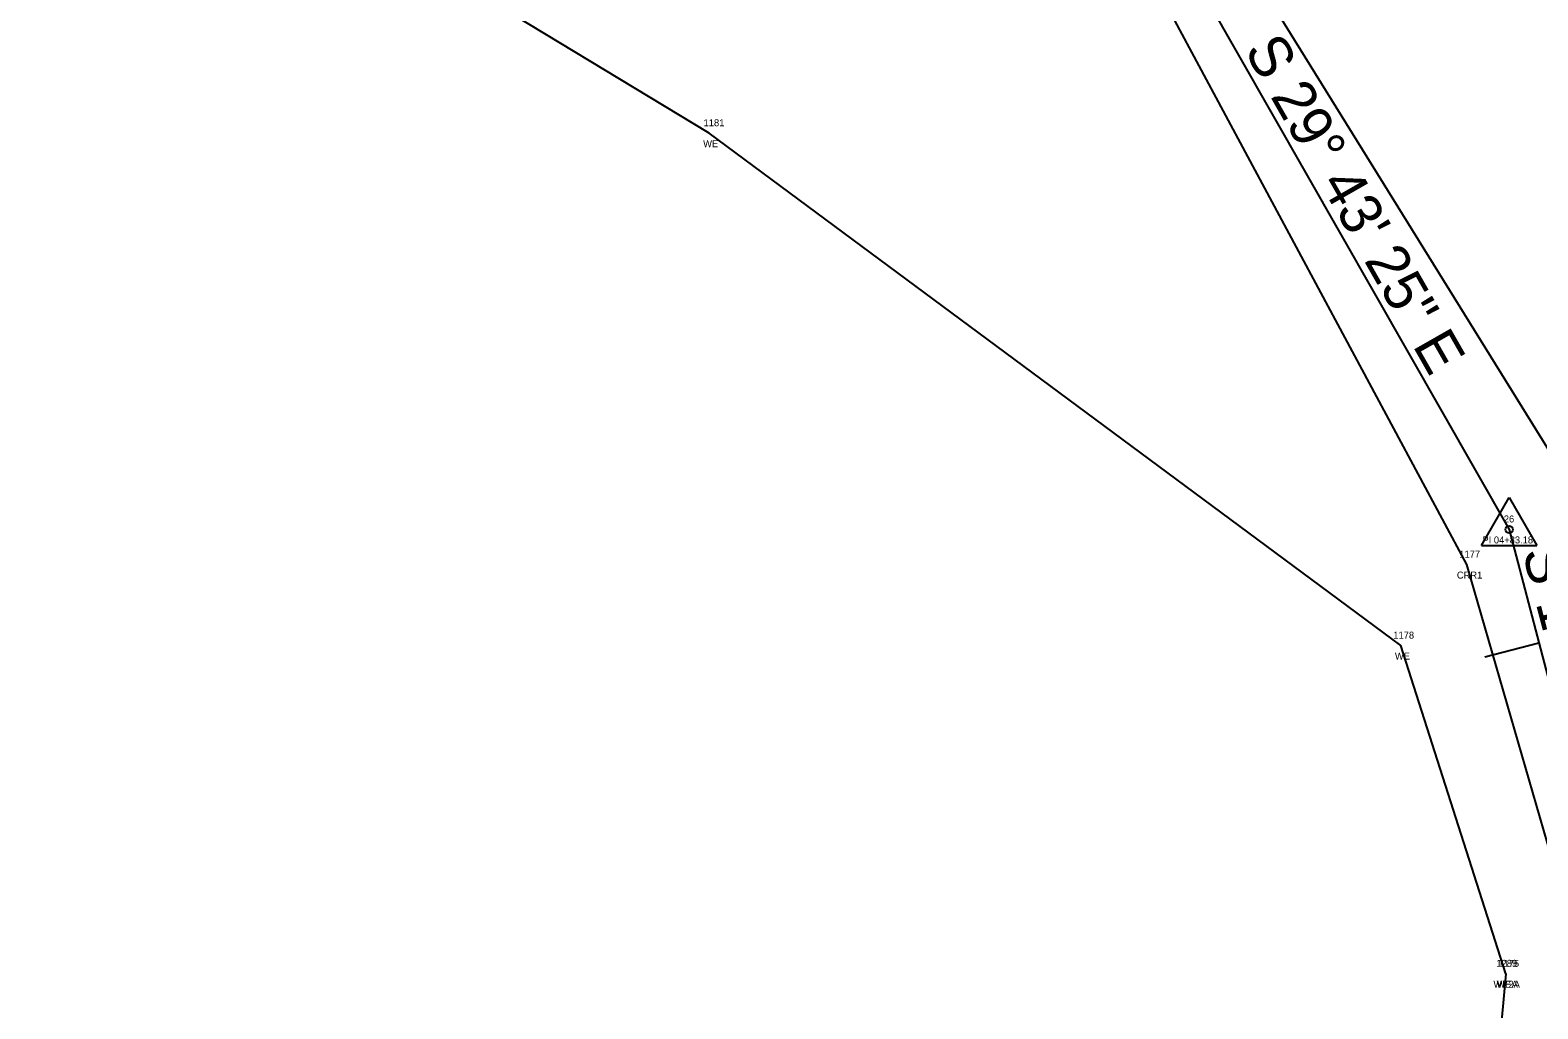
# Model space of a CAD drawing. Extents: x 2445178 to 2446205, y 790762 to 792372.
# Drawn here: x 2445179.6 to 2445395.5, y 791905.3 to 792045.3 of the extents above; entities that cross this region are included whole.
import ezdxf

# ---------------------------------------------------------------- set-up
doc = ezdxf.new("R2010")
doc.units = 0
for name, color, linetype in [('RD_EX_H2O', 7, 'Continuous'), ('RD_EX_H2O_txCode', 7, 'Continuous'), ('RD_HC_Cl', 7, 'Continuous'), ('RD_HC_Data', 7, 'Continuous'), ('RD_HC_Data_Tic', 7, 'Continuous'), ('RD_HC_txCode', 7, 'Continuous'), ('RD_SMD_Locator', 7, 'Continuous')]:
    doc.layers.add(name, color=color, linetype=linetype)

msp = doc.modelspace()

# ---------------------------------------------------------------- linework, layer by layer
at = {"layer": 'RD_EX_H2O'}
for points in [[(2445415.21, 791826.15), (2445411.13, 791915.36), (2445401.26, 791978.48), (2445346.75, 792066.4), (2445347.89, 792130.96), (2445327.72, 792154.04), (2445265.04, 792188.92)], [(2445403.09, 791820.76), (2445401.57, 791912.69), (2445385.3, 791968.86), (2445336.54, 792059.75), (2445337.52, 792129.63), (2445324.7, 792141.79), (2445250.6, 792162.62)], [(2445390.88, 791910.3), (2445375.84, 791957.27), (2445276.8, 792030.59), (2445204.16, 792074.54)], [(2445390.88, 791910.3), (2445382.88, 791823.37), (2445332.21, 791769.8), (2445259.4, 791752.08), (2445179.59, 791723.55)]]:
    msp.add_lwpolyline(points, dxfattribs=at)
at = {"layer": 'RD_HC_Cl'}
for p, q in [((2445340.62, 792062.76), (2445391.36, 791973.89)), ((2445391.36, 791973.89), (2445406.98, 791914.3))]:
    msp.add_line(p, q, dxfattribs=at)
at = {"layer": 'RD_HC_Data'}
for p, q in [((2445387.39, 791971.6), (2445391.36, 791978.48)), ((2445391.36, 791978.48), (2445395.33, 791971.6)), ((2445387.39, 791971.6), (2445395.33, 791971.6))]:
    msp.add_line(p, q, dxfattribs=at)
msp.add_circle((2445391.36, 791973.89), 0.529, dxfattribs=at)
at = {"layer": 'RD_HC_Data_Tic'}
msp.add_line((2445395.62, 791957.63), (2445387.88, 791955.6), dxfattribs=at)
at = {"layer": 'RD_SMD_Locator'}
for centre in [(2445276.8, 792030.59), (2445391.36, 791973.89), (2445385.3, 791968.86), (2445375.84, 791957.27), (2445390.88, 791910.3), (2445390.88, 791910.3)]:
    msp.add_circle(centre, 0.001, dxfattribs=at)

# ---------------------------------------------------------------- texts
at = {"layer": 'RD_EX_H2O_txCode'}
for s, p in [('1181', (2445276.02, 792031.59)), ('WE', (2445275.96, 792028.59)), ('1177', (2445384.23, 791969.86)), ('CRR1', (2445383.88, 791966.86)), ('1178', (2445374.78, 791958.27)), ('WE', (2445375.01, 791955.27)), ('1289', (2445389.53, 791911.3)), ('1175', (2445389.81, 791911.3)), ('WE2A', (2445389.12, 791908.3)), ('WEA', (2445389.57, 791908.3))]:
    msp.add_text(s, height=1, dxfattribs=at).set_placement(p)
at = {"layer": 'RD_HC_Data'}
for s, rotation, p in [('S 29%%d 43\' 25" E', 299.7236, (2445353.35, 792042.48)), ('S 14%%d 41\' 14" E', 284.6871, (2445393.23, 791970.71))]:
    msp.add_text(s, height=6, rotation=rotation, dxfattribs=at).set_placement(p)
at = {"layer": 'RD_HC_txCode'}
for s, p in [('26', (2445390.6, 791974.89)), ('PI 04+83.18', (2445387.54, 791971.89))]:
    msp.add_text(s, height=1, dxfattribs=at).set_placement(p)

doc.saveas('drawing.dxf')
